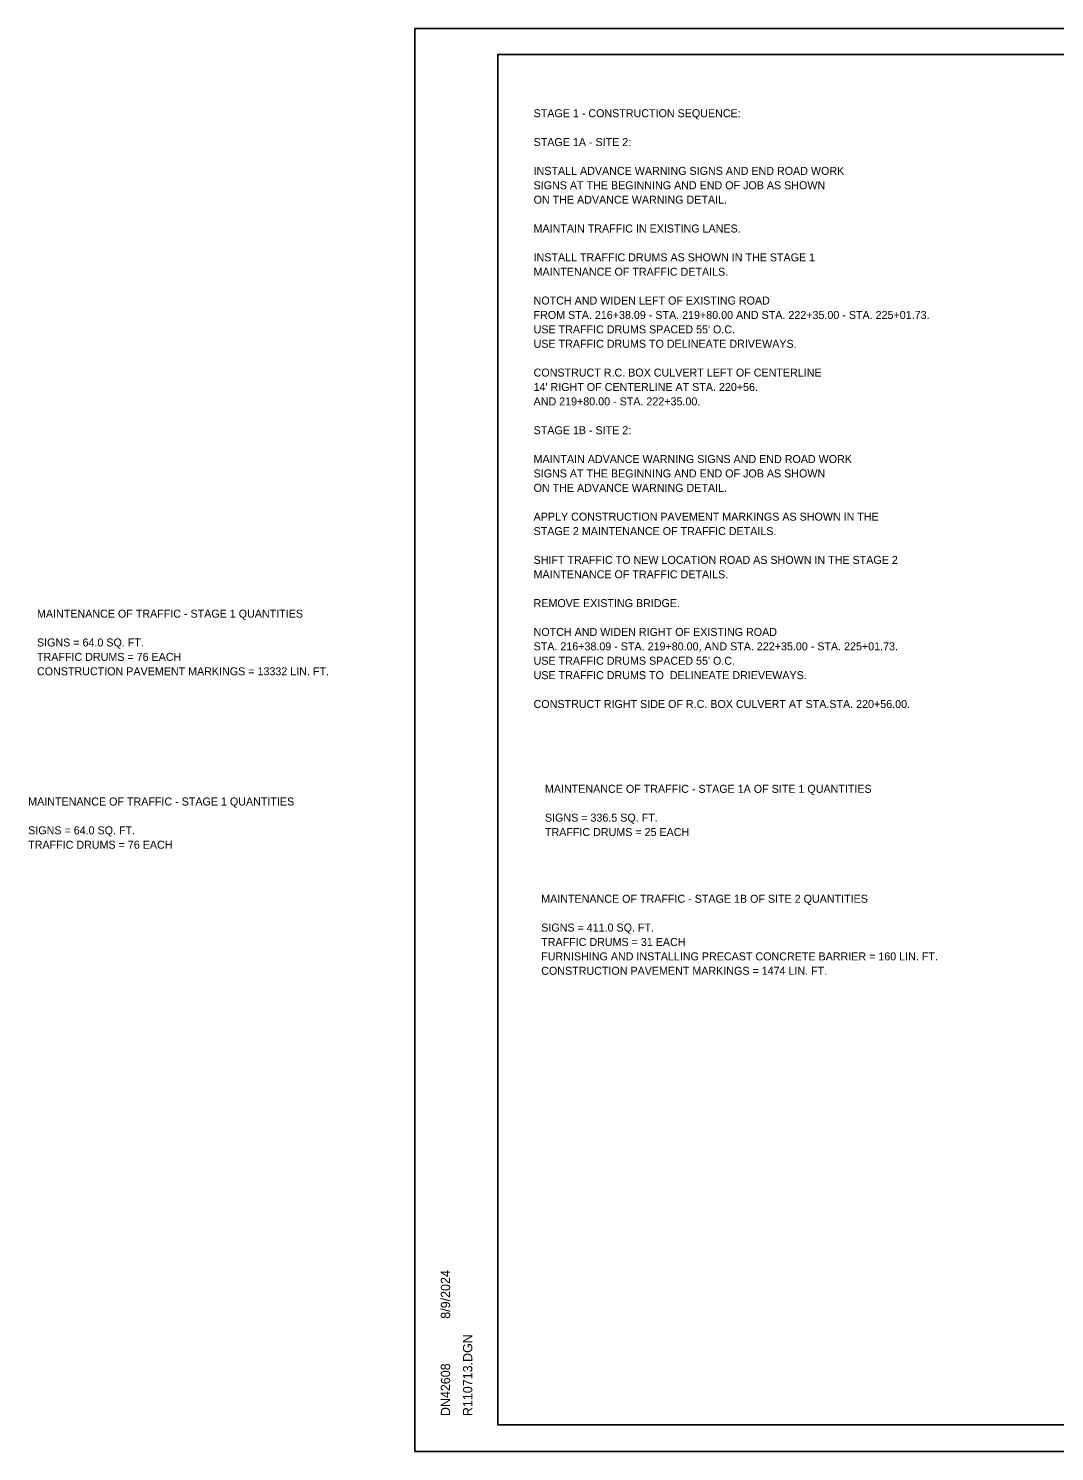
# Model space of a CAD drawing. Extents: x 1678017 to 1687792, y 404433 to 413488.
# Drawn here: x 1681461 to 1682229, y 410689 to 411756 of the extents above; entities that cross this region are included whole.
import ezdxf

# ---------------------------------------------------------------- set-up
doc = ezdxf.new("R2010")
doc.units = 0
for name, color, linetype in [('S_BUILDING', 7, 'Continuous'), ('S_MSC_PT_SYM', 7, 'Continuous'), ('S_STREAM', 7, 'Continuous')]:
    doc.layers.add(name, color=color, linetype=linetype)

msp = doc.modelspace()

# ---------------------------------------------------------------- linework, layer by layer
at = {"layer": 'S_BUILDING'}
for p, q in [((1681812.2, 411736.7), (1683393.1, 411736.7)), ((1681812.2, 410709.4), (1681812.2, 411736.7)), ((1681812.2, 410709.4), (1681812.2, 410709.4)), ((1683393.1, 410709.4), (1681812.2, 410709.4))]:
    msp.add_line(p, q, dxfattribs=at)
at = {"layer": 'S_STREAM'}
for p, q in [((1681750.2, 411756.1), (1683416.9, 411756.1)), ((1681750.2, 410689.5), (1683416.9, 410689.5))]:
    msp.add_line(p, q, dxfattribs=at)
for points in [[(1681750.2, 411756.1), (1683416.9, 411756.1), (1683416.9, 410689.5), (1681750.2, 410689.5)], [(1682981.8, 411736.7), (1683079.9, 411736.7), (1683079.9, 411687.3), (1683160.5, 411687.3), (1683276.5, 411687.3), (1683276.5, 411565.6), (1683393.1, 411565.6), (1683393.1, 410709.4), (1681812.2, 410709.4), (1681812.2, 411736.7)]]:
    msp.add_lwpolyline(points, close=True, dxfattribs=at)

# ---------------------------------------------------------------- texts
at = {"layer": 'S_BUILDING'}
for s, p in [('8/9/2024', (1681776.6, 410789)), ('R110713.DGN', (1681793.2, 410716)), ('DN42608', (1681776.6, 410716))]:
    msp.add_text(s, height=7, rotation=90, dxfattribs=at).set_placement(p)
at = {"layer": 'S_MSC_PT_SYM'}
for s, p in [('STAGE 1 - CONSTRUCTION SEQUENCE:', (1681839.1, 411689.6)), ('STAGE 1A - SITE 2:', (1681839.1, 411668)), ('INSTALL ADVANCE WARNING SIGNS AND END ROAD WORK', (1681839.1, 411646.4)), ('SIGNS AT THE BEGINNING AND END OF JOB AS SHOWN', (1681839.1, 411635.6)), ('ON THE ADVANCE WARNING DETAIL.', (1681839.1, 411624.8)), ('MAINTAIN TRAFFIC IN EXISTING LANES.', (1681839.1, 411603.2)), ('INSTALL TRAFFIC DRUMS AS SHOWN IN THE STAGE 1', (1681839.1, 411581.6)), ('MAINTENANCE OF TRAFFIC DETAILS.', (1681839.1, 411570.8)), ('NOTCH AND WIDEN LEFT OF EXISTING ROAD ', (1681839.1, 411549.2)), ('FROM STA. 216+38.09 - STA. 219+80.00 AND STA. 222+35.00 - STA. 225+01.73.', (1681839.1, 411538.4)), ("USE TRAFFIC DRUMS SPACED 55' O.C.", (1681839.1, 411527.6)), ('USE TRAFFIC DRUMS TO DELINEATE DRIVEWAYS.', (1681839.1, 411516.8)), ('CONSTRUCT R.C. BOX CULVERT LEFT OF CENTERLINE', (1681839.1, 411495.2)), ("14' RIGHT OF CENTERLINE AT STA. 220+56.", (1681839.1, 411484.4)), ('AND 219+80.00 - STA. 222+35.00.', (1681839.1, 411473.6)), ('STAGE 1B - SITE 2:', (1681839.1, 411452)), ('MAINTAIN ADVANCE WARNING SIGNS AND END ROAD WORK', (1681839.1, 411430.4)), ('SIGNS AT THE BEGINNING AND END OF JOB AS SHOWN', (1681839.1, 411419.6)), ('ON THE ADVANCE WARNING DETAIL.', (1681839.1, 411408.8)), ('APPLY CONSTRUCTION PAVEMENT MARKINGS AS SHOWN IN THE', (1681839.1, 411387.2)), ('STAGE 2 MAINTENANCE OF TRAFFIC DETAILS.', (1681839.1, 411376.4)), ('SHIFT TRAFFIC TO NEW LOCATION ROAD AS SHOWN IN THE STAGE 2', (1681839.1, 411354.8)), ('MAINTENANCE OF TRAFFIC DETAILS.', (1681839.1, 411344)), ('REMOVE EXISTING BRIDGE.', (1681839.1, 411322.4)), ('MAINTENANCE OF TRAFFIC - STAGE 1 QUANTITIES', (1681467.1, 411314.5)), ('NOTCH AND WIDEN RIGHT OF EXISTING ROAD ', (1681839.1, 411300.8)), ('SIGNS = 64.0 SQ. FT.', (1681467.1, 411292.9)), ('STA. 216+38.09 - STA. 219+80.00, AND STA. 222+35.00 - STA. 225+01.73.', (1681839.1, 411290)), ('TRAFFIC DRUMS = 76 EACH', (1681467.1, 411282.1)), ("USE TRAFFIC DRUMS SPACED 55' O.C.", (1681839.1, 411279.2)), ('CONSTRUCTION PAVEMENT MARKINGS = 13332 LIN. FT.', (1681467.1, 411271.3)), ('USE TRAFFIC DRUMS TO  DELINEATE DRIEVEWAYS.', (1681839.1, 411268.4)), ('CONSTRUCT RIGHT SIDE OF R.C. BOX CULVERT AT STA.STA. 220+56.00.', (1681839.1, 411246.8)), ('MAINTENANCE OF TRAFFIC - STAGE 1A OF SITE 1 QUANTITIES', (1681847.6, 411183.2)), ('MAINTENANCE OF TRAFFIC - STAGE 1 QUANTITIES', (1681460.5, 411173.7)), ('SIGNS = 336.5 SQ. FT.', (1681847.6, 411161.6)), ('SIGNS = 64.0 SQ. FT.', (1681460.5, 411152.1)), ('TRAFFIC DRUMS = 25 EACH', (1681847.6, 411150.8)), ('TRAFFIC DRUMS = 76 EACH', (1681460.5, 411141.3)), ('MAINTENANCE OF TRAFFIC - STAGE 1B OF SITE 2 QUANTITIES', (1681844.8, 411100.8)), ('SIGNS = 411.0 SQ. FT.', (1681844.8, 411079.2)), ('TRAFFIC DRUMS = 31 EACH', (1681844.8, 411068.4)), ('FURNISHING AND INSTALLING PRECAST CONCRETE BARRIER = 160 LIN. FT.', (1681844.8, 411057.6)), ('CONSTRUCTION PAVEMENT MARKINGS = 1474 LIN. FT.', (1681844.8, 411046.8))]:
    msp.add_text(s, height=6, dxfattribs=at).set_placement(p)

doc.saveas('drawing.dxf')
